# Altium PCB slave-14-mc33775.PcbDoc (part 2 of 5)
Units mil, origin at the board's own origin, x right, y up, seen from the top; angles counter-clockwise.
Board outline 6299.21 x 3937.01 mil, 6 copper layers (Top Copper, Supply, Signal Layer 1, Signal Layer 2, GND, Bot Copper), stack 69.773 mil thick; 428 components, 213 nets, 1149 pads, 1672 vias.
Unrouted connection lines stored in the file: 1.
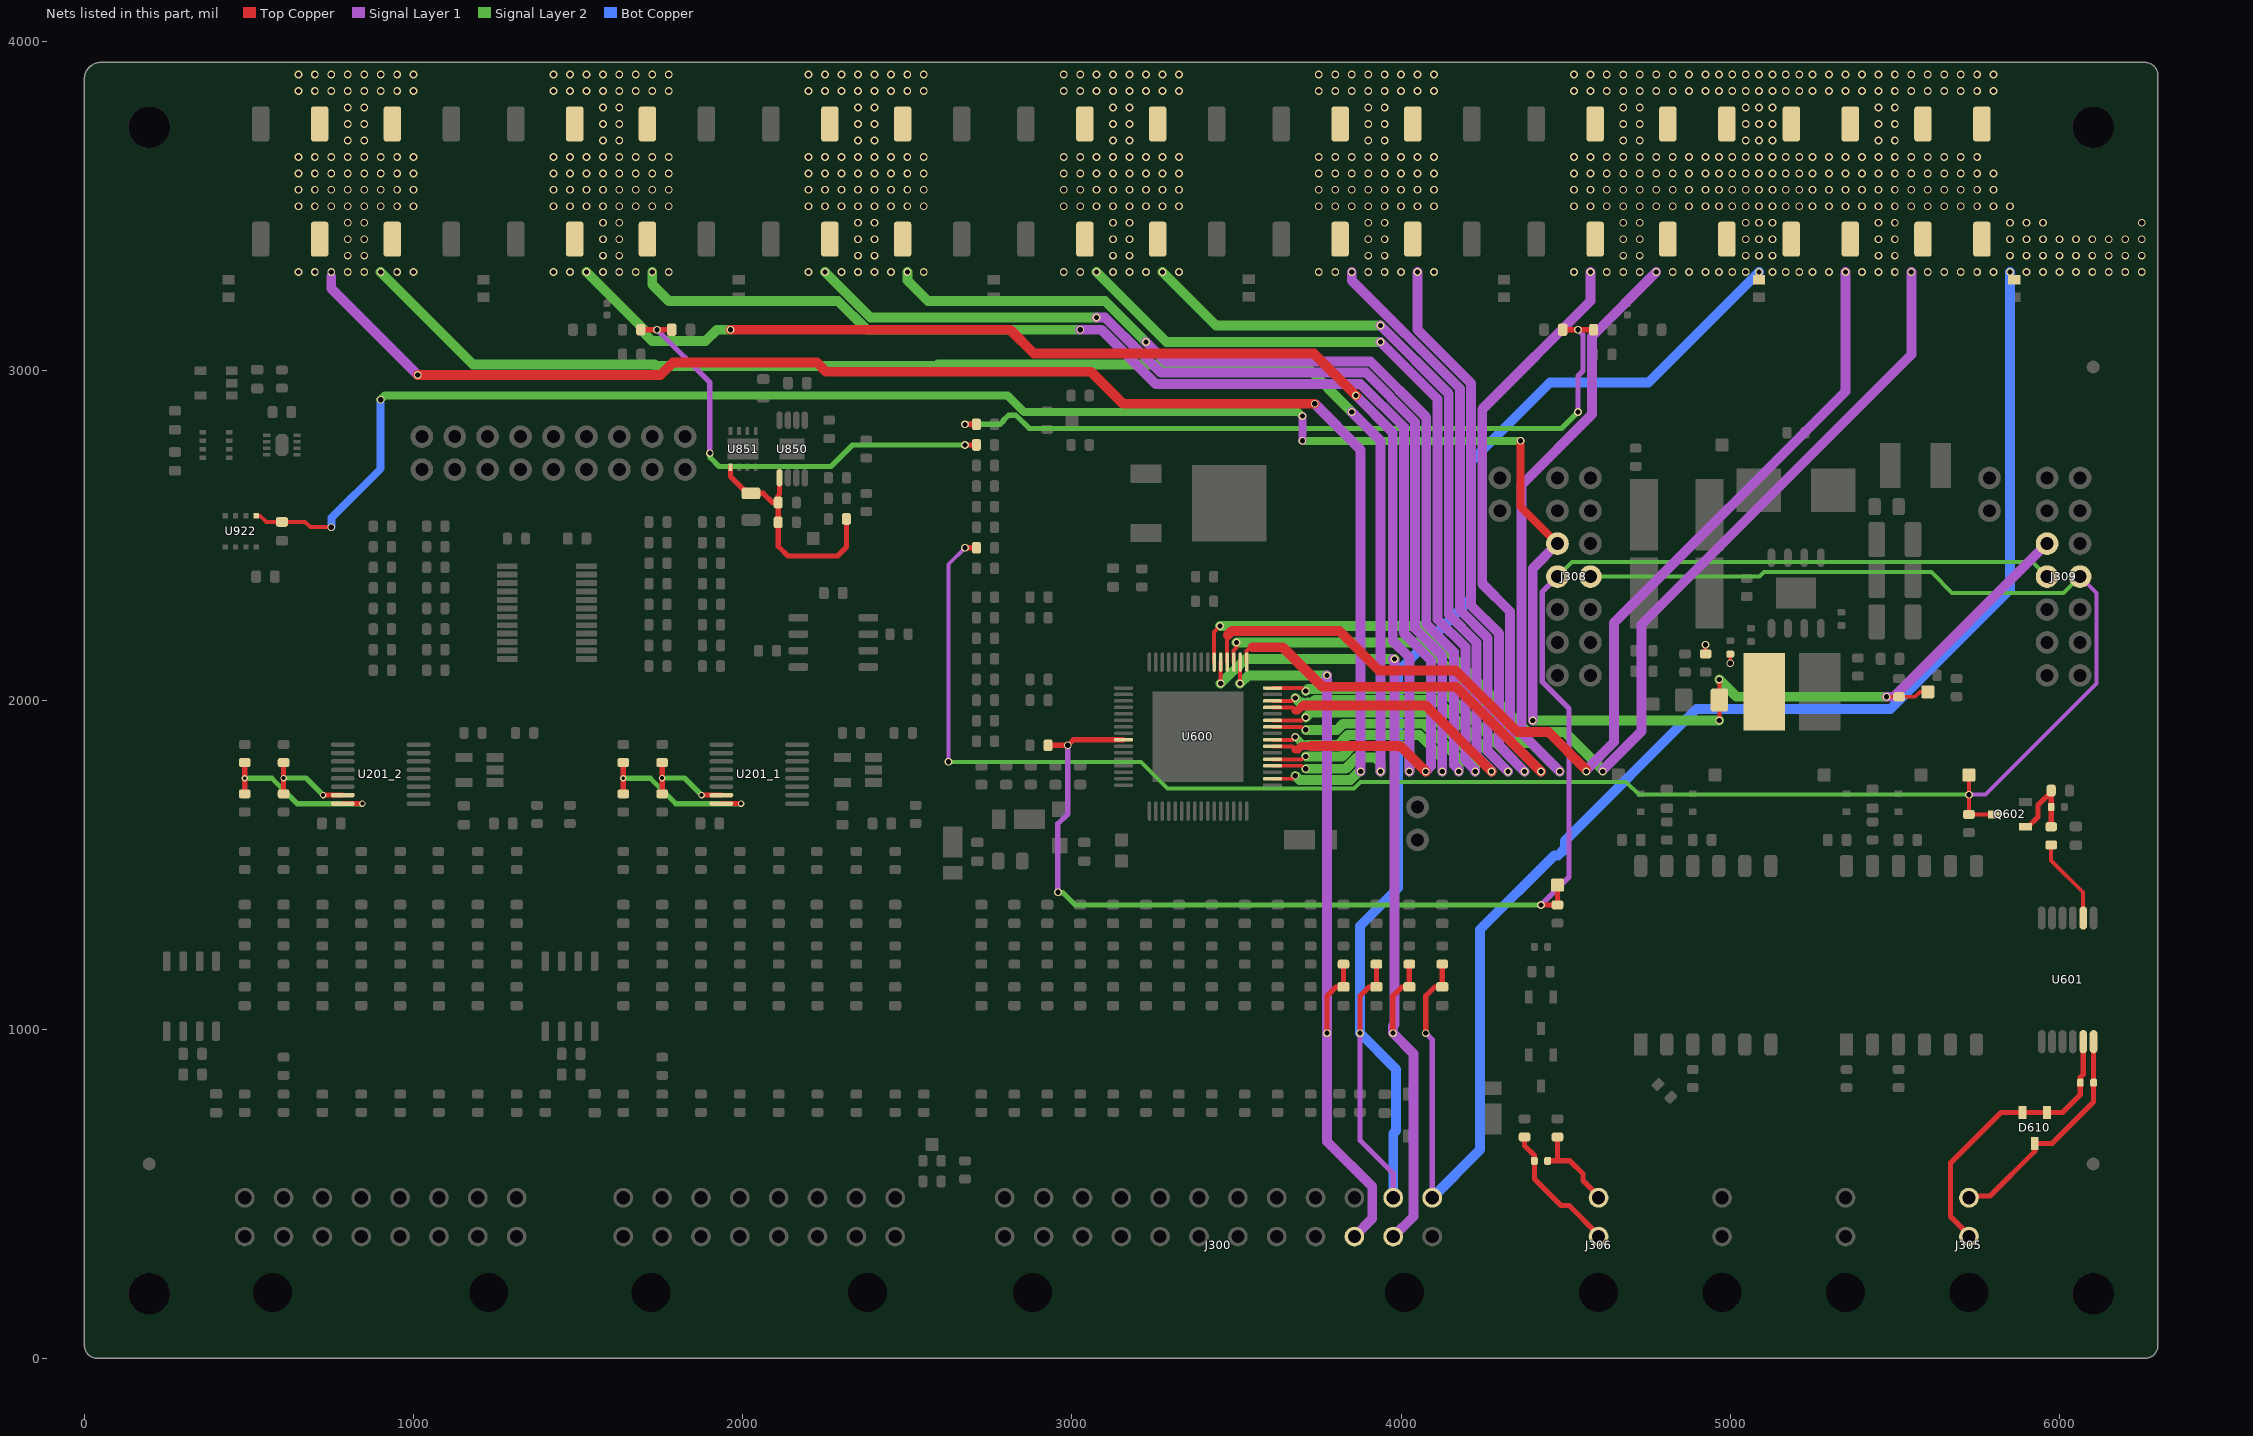
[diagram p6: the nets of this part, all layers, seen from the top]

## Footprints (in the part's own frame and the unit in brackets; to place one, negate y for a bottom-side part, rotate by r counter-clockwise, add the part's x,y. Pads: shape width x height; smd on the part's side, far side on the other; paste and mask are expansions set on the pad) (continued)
PowerDI123 [mm] "PowerDI123, 2-Leads, Body 1,78x3,70mm, IPC Medium Density"
  rect 2.4x1.5 smd: 1(-0.85,0)
  rect 1.05x1.5 smd: 2(1.525,0)
  silkscreen extent -2.05,1.05 -1.95,1.15, body extent -1.85,-0.96 1.85,0.96, height 1
PW0024A_M [mm] "SOP, 24-Leads, Body 7.9x4.5mm, Pitch 0.65mm, IPC Low Density"
  rrect22% 1.6x0.45 smd: 1(-3.05,3.575) 2(-3.05,2.925) 3(-3.05,2.275) 4(-3.05,1.625) 5(-3.05,0.975) 6(-3.05,0.325) 7(-3.05,-0.325) 8(-3.05,-0.975) 9(-3.05,-1.625) 10(-3.05,-2.275) 11(-3.05,-2.925) 12(-3.05,-3.575) 13(3.05,-3.575) 14(3.05,-2.925) 15(3.05,-2.275) 16(3.05,-1.625) 17(3.05,-0.975) 18(3.05,-0.325) 19(3.05,0.325) 20(3.05,0.975) 21(3.05,1.625) 22(3.05,2.275) 23(3.05,2.925) 24(3.05,3.575)
  silkscreen extent -3.17,-3.95 1.85,4.47, body extent -3.21,-3.9 3.21,3.9, height 1
R-PDSO-G8 [mm] "SOIC, 8-Leads, Body 4,90x3,90mm, Pitch 1,27mm, Thermal Pad 3,10x2,40mm, IPC Medium Density"
  oval 1.45x0.6 smd: 1(-2.725,1.905) 2(-2.725,0.635) 3(-2.725,-0.635) 4(-2.725,-1.905) 5(2.725,-1.905) 6(2.725,-0.635) 7(2.725,0.635) 8(2.725,1.905)
  rect 2.4x3.1 smd: 9(0,0)
  silkscreen extent -2.85,-2.5 1.6,2.88, body extent -3,-2.5 3,2.5, height 1.7
RESC1005X04N [mm] "Chip Resistor, 2-Leads, Body 1,00x0,50mm, IPC Medium Density"
  rrect50% 0.55x0.55 smd: 1(-0.45,0) 2(0.45,0)
  body extent -0.53,-0.28 0.53,0.28, height 0.4
RESC1608X05N [mm] "Chip Resistor, 2-Leads, Body 1,60x0,80mm, IPC Medium Density"
  rrect50% 0.7x0.9 smd: 1(-0.7,0) 2(0.7,0)
  body extent -0.85,-0.45 0.85,0.45, height 0.45
RESC2012X05N [mm] "Chip Resistor, 2-Leads, Body 2,00x1,20mm, IPC Medium Density"
  rrect40% 0.95x1.3 smd: 1(-0.925,0) 2(0.925,0)
  silkscreen extent -0.05,-0.55 0.05,0.55, body extent -1.05,-0.65 1.05,0.65, height 0.5
RESC5025X07N [mm] "Chip Resistor, 2-Leads, Body 5,00x2,50mm, IPC Medium Density"
  rrect30% 1.35x2.7 smd: 1(-2.275,0) 2(2.275,0)
  silkscreen extent -1.2,-1.25 1.2,1.25, body extent -2.6,-1.35 2.6,1.35, height 0.7
S1MSP1 [mm] "SODFL, 2-Leads, Body 1,78x3,70mm, IPC Medium Density"
  rect 2.4x1.5 smd: 1(0.85,0)
  rect 1.05x1.5 smd: 2(-1.525,0)
  silkscreen extent 1.73,-1.07 1.83,-0.97, body extent -1.85,-0.96 1.85,0.96, height 1
SHT3X [mm] "SON, 8-Leads, Body 2,50x2,50mm, Pitch 0,50mm, Thermal Pad 1,80x1,09mm, IPC Medium Density"
  rect 0.55x0.25 smd: 1(-1.17,0.75) 2(-1.17,0.25) 3(-1.17,-0.25) 4(-1.17,-0.75) 5(1.17,-0.75) 6(1.17,-0.25) 7(1.17,0.25) 8(1.17,0.75)
  oct 1x1.7 smd: 9(0,0)
  Top Copper region: 0,-0.849 0.5,-0.849 0.5,0.851 0,0.851
  Top Copper region: -0.499,-0.85 0.001,-0.85 0.001,0 -0.499,0
  silkscreen extent -1.9,-1.45 1.45,1.5, body extent -1.25,-1.25 1.25,1.25, height 0.9
SOD523_PESD_NEXPERIA [mm] "SODFL, 2-Leads, Body 0,80x1,60mm, IPC Medium Density"
  rect 0.5x0.6 smd: 1(-0.7,0) 2(0.7,0)
  silkscreen extent -0.9,0.55 -0.8,0.65, body extent -0.8,-0.43 0.8,0.43, height 0.65
SOIC127P600X175-8N [mm] "SOIC, 8-Leads, Body 4,90x3,90mm, Pitch 1,27mm, IPC Medium Density"
  rrect50% 1.5x0.6 smd: 1(-2.7,1.905) 2(-2.7,0.635) 3(-2.7,-0.635) 4(-2.7,-1.905) 5(2.7,-1.905) 6(2.7,-0.635) 7(2.7,0.635) 8(2.7,1.905)
  silkscreen extent -2.8,-2.45 1.55,2.8, body extent -3,-2.45 3,2.45, height 1.75
SOT95P237X110-3N [mm] "SOT23, 3-Leads, Body 2,92x2,37mm, Pitch 0,95mm, IPC Medium Density"
  rect 1x0.6 smd: D(1.2,0) G(-1.2,0.95) S(-1.2,-0.95)
  silkscreen extent -0.3,-1.5 0.7,1.5, body extent -1.32,-1.52 1.32,1.52, height 1.1
SOT-23-OT5_L [mm] "SOT23, 5-Leads, Body 2.9x1.7mm, Pitch 0.95mm, Lead Span 2.8mm, IPC High Density"
  rect 0.9x0.65 smd: 1(-1.2,0.95) 2(-1.2,0) 3(-1.2,-0.95) 4(1.2,-0.95) 5(1.2,0.95)
  silkscreen extent -1.33,-1.55 0.35,1.95, body extent -0.9,-1.55 0.9,1.55, height 1.45
SRP7028A [mm] "Bourns SRP7028A Series"
  rect 3.45x3.35 smd: 1(-2.875,0) 2(2.875,0)
  silkscreen extent -3.8,-3.45 3.8,3.45, body extent -3.45,-3.3 3.45,3.3, height 2.86
Testpoint_S1 [mm] "Testpunkt, quardratisch 1mm"
  rrect20% 1x1 smd paste-0.5: 1(0,0)
TPS7A16_VSON [mm] "SON, 8-Leads, Body 3,00x3,00mm, Pitch 0,65mm, Thermal Pad 2,40x1,49mm, IPC Medium Density"
  rect 0.6x0.3 smd: 1(-1.4,0.975) 2(-1.4,0.325) 3(-1.4,-0.325) 4(-1.4,-0.975) 5(1.4,-0.975) 6(1.4,-0.325) 7(1.4,0.325) 8(1.4,0.975)
  rect 1.65x2.4 smd: 9(0,0)
  silkscreen extent -2.15,-1.7 1.7,1.75, body extent -1.55,-1.55 1.55,1.55, height 1
TPS7A16A-Q1 [mm] "TSOP, 8-Leads, Body 3,00x3,00mm, Pitch 0,65mm, Thermal Pad 1,92x1,60mm, IPC Medium Density"
  oval 1.35x0.5 smd: 1(-2.225,0.975) 2(-2.225,0.325) 3(-2.225,-0.325) 4(-2.225,-0.975) 5(2.225,-0.975) 6(2.225,-0.325) 7(2.225,0.325) 8(2.225,0.975)
  rect 1.6x1.92 smd: 9(0,0)
  silkscreen extent -2.35,-1.55 1.15,1.9, body extent -2.45,-1.55 2.45,1.55, height 1.1
TYS6045470M-10 [mm] "Precision Wire Wound Inductor, 2-Leads, Body 6,00x6,00mm, IPC Medium Density"
  rect 3.2x6 smd: 1(-2.15,0) 2(2.15,0)
  silkscreen extent -4.05,-3.15 0.15,3.15, body extent -3.1,-3 3.1,3, height 4.8
Vishay_THJP_0603 [mm] "ThermaWick Ceramic thermal coupling, 2-Leads, Body 1,55x0,84mm, IPC Medium Density"
  rect 0.75x0.95 smd: 1(-0.675,0) 2(0.675,0)
  body extent -0.84,-0.49 0.84,0.49, height 0.89

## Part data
3.3V_DCDC 3.3V_LDO ALARM_IN ALARM_OUT enable_DCDC GND TPL_H_N TPL_H_P TPL_L_N TPL_L_P Vaux Vbat Vbat_con_ext Vddc Vin_DCDC Vmodule: "Testpoint, square"
C200_1 C200_2 C203_1 C203_2 C220_1 C220_2: library part gen_C_ceramic_1u_35V_X7R_0603, "MLCC", Capacitance=1u, Case EIA=0603, Case Metric=1608, Dielectric=X7R, Operating Temperature="-55°C - +125°C", PnP Package=0603C, PnP Value=1uF/35V/X7R, Rated Voltage=35V, Supplier Part Number 1=2906941
C201_1 C201_2 C212_1 C212_2 C213_1 C213_2 C214_1 C214_2 C215_1 C215_2 C216_1 C216_2 C217_1 C217_2 C218_1 C218_2 C219_1 C219_2 C221_1 C221_2 C400 C601 C603 C604 C605 C606 C613 C617 C807 C850 C852 C900 C920 C921 C922 C923 C924 C925: library part gen_C_ceramic_100n_100V_X7R_0603, "MLCC", Capacitance=100n, Case EIA=0603, Case Metric=1608, Dielectric=X7R, PnP Package=0603C, Rated Voltage=100V, Supplier Part Number 1=490-13420-1-ND
C202_1 C202_2 C204_1 C204_2 C205_1 C205_2 C206_1 C206_2 C207_1 C207_2 C208_1 C208_2 C209_1 C209_2 C210_1 C210_2 C211_1 C211_2 C607 C610: library part gen_C_ceramic_10n_100V_X7R_0603, "MLCC", Capacitance=10n, Case EIA=0603, Case Metric=1608, Dielectric=X7R, PnP Package=0603C, PnP Value=10nF/100V/X7R, Rated Voltage=100V, Supplier Part Number 1=1301715
C500 C501 C502 C503 C504 C505 C506 C507 C508 C509 C510 C511 C512 C513 C514 C515 C516 C517 C518 C519 C520 C521 C522 C523 C524 C525 C526 C527 C528 C529 C530 C531 C600 C700 C701 C702 C703: library part gen_C_ceramic_47n_100V_X7R_0603, "MLCC", Capacitance=47n, Case EIA=0603, Case Metric=1608, Dielectric=X7R, PnP Package=0603C, Rated Voltage=100V, Supplier Part Number 1=2478249
C602 C608 C609 C612: library part gen_C_ceramic_220p_50V_C0G_0603, "MLCC", Capacitance=220p, Case EIA=0603, Case Metric=1608, Dielectric=C0G, PnP Package=0603C, Rated Voltage=50V, Supplier Part Number 1=603-AC603JRNPO9BN221
C611: library part gen_C_ceramic_470n_50V_X7R_0603, "MLCC", Capacitance=470n, Case EIA=0603, Case Metric=1608, Dielectric=X7R, PnP Package=0603C, Rated Voltage=50V, Supplier Part Number 1=2547051
C614 C615 C616 C618: library part gen_C_ceramic_22p_50V_C0G_0402, "MLCC", Capacitance=22p, Case EIA=0402, Case Metric=1005, Dielectric=C0G, PnP Package=0402C, Rated Voltage=50V, Supplier Part Number 1=1856067, Tolerance=1%
C800 C801: library part gen_C_ceramic_15u_100V_X7R_2220, "Stacked MLCC", Capacitance=15u, Case EIA=2220, Case Metric=5750, Dielectric=X7R, Rated Voltage=100V, Supplier Part Number 1=2781468
C802 C803: library part gen_C_ceramic_1u_100V_X7R_1210, "MLCC", Capacitance=1u, Case EIA=1210, Case Metric=3225, Dielectric=X7R, Rated Voltage=100V, Supplier Part Number 1=1301722
C804: library part gen_C_ceramic_3u3_100V_X7R_1812, "MLCC", Capacitance=3u3, Case EIA=1812, Case Metric=4532, Dielectric=X7R, Rated Voltage=100V, Supplier Part Number 1=2579025
C805 C808: library part gen_C_ceramic_2n2_100V_X7R_0402, "MLCC", Capacitance=2n2, Case EIA=0402, Case Metric=1005, Dielectric=X7R, PnP Package=0402C, Rated Voltage=100V, Supplier Part Number 1=490-4911-1-ND
C806: library part gen_C_ceramic_2u2_100V_X7R_1210, "MLCC", Capacitance=2u2, Case EIA=1210, Case Metric=3225, Dielectric=X7R, Rated Voltage=100V, Supplier Part Number 1=2781417
C809: library part gen_C_ceramic_100p_200V_C0G_0402, "MLCC", Capacitance=100p, Case EIA=0402, Case Metric=1005, Dielectric=C0G, PnP Package=0402C, Rated Voltage=200V, Supplier Part Number 1=2426878, Tolerance=5%
C810: library part gen_C_ceramic_22u_6V3_X7R_1206, "MLCC", Capacitance=22u, Case EIA=1206, Case Metric=3216, Dielectric=X7R, Rated Voltage=6.3V, Supplier Part Number 1=2672216
C851: library part gen_C_ceramic_2u2_10V_X7R_0805, "MLCC", Capacitance=2u2, Case EIA=0805, Case Metric=2012, Dielectric=X7R, Rated Voltage=10V, Supplier Part Number 1=2478259
D600 D601 D608: "Schottky Diode", Breakdown Voltage=100V, Continuous Forward Current=1A, Manufacturer="Diodes Inc.", Operating Temperature="−55°C - +175°C", PnP Package=POWERDI123, Supplier Part Number 1=621-DFLS1-100Q-7
D602: "400W Transient Voltage Suppressor", Breakdown Voltage=70.20V, Manufacturer=Nexperia, Operating Temperature="-55°C - +150°C", Part Name=PTVSxS1UR, Supplier Part Number 1=771-PTVS60VS1UR115
D603: "1.0A surface mount glass passivated rectifier", Breakdown Voltage=1000V, Continuous Forward Current=1A, Manufacturer="Diodes Inc.", Operating Temperature="-55°C - +150°C", Supplier Part Number 1=621-S1MSP1-7
D604 D605 D606 D607: "Very low capacitance bidirectional ESD protection diode", Breakdown Voltage=6.8V, Manufacturer=Nexperia, Operating Temperature="-55°C - +150°C", PnP Package=SOD523, Supplier Part Number 1=771-PESD5V0V1BB115
D609 D610: "ESD-Schutzbaustein", Breakdown Voltage=8V, Manufacturer="ON Semiconductor", PnP Package=SOT23-3, Supplier Part Number 1=2317483
FD_LL FD_LR FD_UR: library part Fiducial_2
IC920: library part CMP-0192-00211-1, "2-Wire High-Accuracy Temperature Sensor, Slave Address 000, 5-Pin SOT-23, -55°C to +125°C Temperature, Tape and Reel"
J300: "Micro-Fit 3.0 Right Angle Header, 3.00mm Pitch, Dual Row, 24 Circuits, with Snap-in Plastic Peg PCB Lock, Tin, Glow Wire Capable, Black, 43045-2400", Manufacturer=Molex, Operating Temperature="-40°C - +105°C", Part Name=MicroFit, Rated Current=8.5A, Rated Voltage=600V, Supplier Part Number 1=1012245
J301 J302 J305 J306: "Micro-Fit 3.0 Right Angle Header, 3.00mm Pitch, Dual Row, 2 Circuits, with Snap-in Plastic Peg PCB Lock, Tin, Glow Wire Capable, Black, 43045-0200", Manufacturer=Molex, Operating Temperature="-40°C - +105°C", Part Name=MicroFit, Rated Current=8.5A, Rated Voltage=600V, Supplier Part Number 1=1012251
J303: "Standard Pinheader, THD, gerade, 2.54mm, 2-reihig", Operating Temperature="−40 °C - +105 °C", Part Name=PinHeader, Rated Current=3A, Rated Voltage=250V, Supplier Part Number 1=2025256
J304 J307: "Micro-Fit 3.0 Right Angle Header, 3.00mm Pitch, Dual Row, 16 Circuits, with Snap-in Plastic Peg PCB Lock, Tin, Glow Wire Capable, Black, 43045-1600", Manufacturer=Molex, Operating Temperature="-40°C - +105°C", Part Name=MicroFit, Rated Current=8.5A, Rated Voltage=600V, Supplier Part Number 1=9961380
J308 J309: "Standard Pinheader, THD, gerade, 2.54mm, 2-reihig", Operating Temperature="−40 °C - +105 °C", Part Name=PinHeader, Rated Current=3A, Rated Voltage=250V, Supplier Part Number 1=200-TSW10707GD
J310 J311 J312: "Standard Pinheader, THD, gerade, 2.54mm", Operating Temperature="−40 °C - +105 °C", Part Name=PinHeader, Rated Current=3A, Rated Voltage=250V, Supplier Part Number 1=2505044
L800: library part SRP7028A-R47M, "FIXED IND 470NH 17.5A 4.2 MOHM", Manufacturer="Bourns Inc", Operating Temperature="-40°C - +150°C", Rated Current=17.5A, Saturation Current=26A, Supplier Part Number 1=SRP7028A-R47MCT-ND
L801: library part TYS6045470M-10, "Power Inductor", Manufacturer="Laird-Signal Integrity Products", Operating Temperature="-55°C - +150°C", Rated Current=1.2A, Saturation Current=1.4A, Supplier Part Number 1=240-2745-1-ND
LD600 LD601 LD800 LD850: library part LED_0603_green_AECQ, "TLMG1100-GS08", Breakdown Voltage=5V, Continuous Forward Current=20mA, Forward Voltage @ 20mA=2.1V, Manufacturer=Vishay, Operating Temperature="-40°C - 100°C", PnP Package=LED_0603, Supplier Part Number 1=2293494
MP_LL MP_LR MP_UL MP_UR: "Hole, M3, with Isolation"
Q600: "100V, 3A NPN high power bipolar transistor", Manufacturer=Nexperia, Operating Temperature="-55°C - +150°C", Part Name=MJD31CA, Supplier Part Number 1=771-MJD31CAJ
Q601 Q602: "MOSFET-Transistor, n-Kanal, 1.6 A, 100 V, 0.250 ohm", Manufacturer=Diodes, Maximum Continous Drain Current (25°C)=1.6A, Maximum Drain-Source Voltage=100V, Operating Temperature="-55°C - +150°C", Part Name=NMOS, Supplier Part Number 1=DMN10H220L-7DICT-ND
R100 R200_1 R200_2 R201_1 R201_2 R202_1 R202_2 R203_1 R203_2 R204_1 R204_2 R205_1 R205_2 R210_1 R210_2 R211_1 R211_2 R212_1 R212_2 R213_1 R213_2 R214_1 R214_2 R215_1 R215_2 R216_1 R216_2 R217_1 R217_2 R230_1 R230_2 R232_1 R232_2 R516 R517 R518 R519 R520 R521 R522 R523 R524 R525 R526 R601 R602 R603 R606 R607 R608 R609 R610 R612 R613 R614 R615 R619 R620 R622 R623 R624 R625 R626 R629 R630 R631 R633 R635 R636 R637 R639 R640 R801 R803 R807 R850 R851 R853: library part gen_R_0R_0603, "SMD Resistor 0R 0603", Case EIA=0603, Case Metric=1608, Maximum Working Voltage=75V, Operating Temperature="-55°C - +155°C", PnP Package=0603R, Power=0.1W, Supplier Part Number 1=2616580
R206_1 R206_2 R207_1 R207_2 R208_1 R208_2 R209_1 R209_2 R218_1 R218_2 R219_1 R219_2 R220_1 R220_2 R221_1 R221_2 R500 R501 R502 R503 R504 R505 R506 R507 R508 R509 R510 R511 R512 R513 R514 R515 R700 R701 R702 R703 R810 R916 R920: library part gen_R_10k_0603, "SMD Resistor 10k 0603", Case EIA=0603, Case Metric=1608, Maximum Working Voltage=75V, Operating Temperature="-55°C - +155°C", PnP Package=0603R, Power=0.1W, Supplier Part Number 1=2073349, Tolerance=1%
R222_1 R222_2 R223_1 R223_2 R224_1 R224_2 R225_1 R225_2 R226_1 R226_2 R227_1 R227_2 R228_1 R228_2 R229_1 R229_2 R231_1 R231_2: library part gen_R_1k_0603, "SMD Resistor 1k 0603", Case EIA=0603, Case Metric=1608, Maximum Working Voltage=75V, Operating Temperature="-55°C - +155°C", PnP Package=0603R, Power=0.1W, Supplier Part Number 1=1652848, Tolerance=1%
R400 R401 R616 R617 R627 R641: library part gen_R_5k1_0603, "SMD Resistor 5k1 0603", Case EIA=0603, Case Metric=1608, Maximum Working Voltage=75V, Operating Temperature="-55°C - +155°C", PnP Package=0603R, Power=0.1W, Supplier Part Number 1=667-ERJ-3GEYJ512V, Tolerance=5%
R600: library part gen_R_10R_0805, "SMD Resistor 10R 0805", Case EIA=0805, Case Metric=2012, Maximum Working Voltage=150V, Operating Temperature="-55°C - +155°C", PnP Package=0805R, Power=0.125W, Supplier Part Number 1=1750728, Tolerance=1%
R604: library part gen_R_270R_0603, "SMD Resistor 270R 0603", Case EIA=0603, Case Metric=1608, Maximum Working Voltage=75V, Operating Temperature="-55°C - +155°C", PnP Package=0603R, Power=0.1W, Supplier Part Number 1=2141320, Tolerance=1%
R605: library part gen_R_2k7_0603, "SMD Resistor 2k7 0603", Case EIA=0603, Case Metric=1608, Maximum Working Voltage=75V, Operating Temperature="-55°C - +155°C", PnP Package=0603R, Power=0.1W, Tolerance=1%
R611 R621 R628 R632 R634 R642: library part gen_R_150R_0603, "SMD Resistor 150R 0603", Case EIA=0603, Case Metric=1608, Maximum Working Voltage=75V, Operating Temperature="-55°C - +155°C", PnP Package=0603R, Power=0.1W, Supplier Part Number 1=2303076, Tolerance=1%
R618: library part gen_R_4R53_0603, "SMD Resistor 4R53 0603", Case EIA=0603, Case Metric=1608, Maximum Working Voltage=75V, Operating Temperature="-55°C - +155°C", PnP Package=0603R, Power=0.1W, Tolerance=1%
R638 R643 R808 R900 R901 R902 R903 R904 R905 R906 R907 R908 R909 R910 R911 R912 R913 R914 R915 R917 R918 R919 R921 R922 R923 R924 R925 R926 R927 R928 R929 R930 R931 R932 R933: library part gen_R_100k_0603, "SMD Resistor 100k 0603", Case EIA=0603, Case Metric=1608, Maximum Working Voltage=75V, Operating Temperature="-55°C - +155°C", PnP Package=0603R, Power=0.1W, Supplier Part Number 1=2303232, Tolerance=1%
R704 R705: library part gen_R_10k_NTC_0402, "SMD Resistor 10k NTC 0402", Case EIA=0402, Maximum Working Voltage=50V, Operating Temperature="-40°C - +150°C", Power=0.150W, Supplier Part Number 1=2432559
R706 R707 R708 R709 R710 R711 R712 R713: library part Vishay_THJP_0603, "ThermaWick thermal coupling 0603", Case EIA=0603, Maximum Working Voltage=1.5kV, Supplier Part Number 1=71-THJP0603AST1
R714 R715 R716 R717 R718 R719 R720 R721 R722 R723 R724 R725 R726 R727 R728 R729 R730 R731 R732 R733 R734 R735 R736 R737 R738 R739 R740 R741: library part gen_R_68R_2010, "SMD Resistor 68R 2010", Case EIA=2010, Case Metric=5025, Maximum Working Voltage=200V, Operating Temperature="-55°C - +155°C", PnP Package=2010R, Power=0.75W, Supplier Part Number 1=2323988, Tolerance=1%
R800: library part gen_R_100R_0603, "SMD Resistor 100R 0603", Case EIA=0603, Case Metric=1608, Maximum Working Voltage=75V, Operating Temperature="-55°C - +155°C", PnP Package=0603R, Power=0.1W, Supplier Part Number 1=P100HCT-ND, Tolerance=1%
R802: library part gen_R_0R1_0805, "SMD Resistor 0R1 0805", Case EIA=0805, Maximum Working Voltage=150V, Operating Temperature="-55°C - +155°C", Power=250mW, Supplier Part Number 1=2824733
R804 R854: library part gen_R_240R_0603, "SMD Resistor 240R 0603", Case EIA=0603, Case Metric=1608, Maximum Working Voltage=75V, Operating Temperature="-55°C - +155°C", PnP Package=0603R, Power=0.1W, Supplier Part Number 1=667-ERJ-3EKF2400V, Tolerance=1%
R805: library part gen_R_287k_0603, "SMD Resistor 287k 0603", Case EIA=0603, Case Metric=1608, Maximum Working Voltage=75V, Operating Temperature="-55°C - +155°C", PnP Package=0603R, Power=0.1W, Supplier Part Number 1=667-ERJ-3EKF2873V, Tolerance=1%
R806: library part gen_R_174k_0603, "SMD Resistor 174k 0603", Case EIA=0603, Case Metric=1608, Maximum Working Voltage=75V, Operating Temperature="-55°C - +155°C", PnP Package=0603R, Power=0.1W, Supplier Part Number 1=667-ERJ-3EKF1743V, Tolerance=1%
R809: library part gen_R_27k4_0603, "SMD Resistor 27k4 0603", Case EIA=0603, Case Metric=1608, Maximum Working Voltage=75V, Operating Temperature="-55°C - +155°C", PnP Package=0603R, Power=0.1W, Supplier Part Number 1=667-ERJ-3EKF2742V, Tolerance=1%
R852: library part gen_R_1M_0603, "SMD Resistor 1M 0603", Case EIA=0603, Case Metric=1608, Maximum Working Voltage=75V, Operating Temperature="-55°C - +155°C", PnP Package=0603R, Power=0.1W, Supplier Part Number 1=1469746, Tolerance=1%
T600 T601: "Pulse HM2102NLT BMS Transformer", Manufacturer=Pulse, Operating Temperature="-40°C - +125°C", Supplier Part Number 1=673-HM2102NLT
U200_1 U200_2: "Ultralow Noise, High Accuracy 4.096V Reference", Manufacturer="Analog Devices", Operating Temperature="−40°C - +125°C", PnP Package=SO-8, Supplier Part Number 1=2112692
U201_1 U201_2: library part CMP-0798-00197-1, "CMOS, Low Voltage, 2-Wire Serially Controlled, Matrix Switch, -40 to 85 degC, 16-pin SOP (RU-16), Tube", Manufacturer="Analog Devices"
U202_1 U202_2: library part CMP-0384-01512-2, "Single Channel RRIO Operational Amplifier, 2.5 MHz BW, 1 V/us SR, Industrial, 5-pin SOT23 (RJ-5), Reel", Amplifiers Per Package=1, Generic Part Number=AD8628, Input Bias Current=30pA, Input Offset Voltage=1uV, Manufacturer="Analog Devices"
U400: "Automotive 2-Mbit serial I²C  / bus EEPROM with 1 MHz clock", Manufacturer=STMicroelectronics, Operating Temperature="-40°C - +125°C", PnP Package=SO8N, Supplier Part Number 1=497-16238-1-ND
U600: "14 Cells Battery Cell Controller IC", Manufacturer=NXP, Operating Temperature="−40°C - +125°C"
U601: "15MBd Dual-channel Bi-directional Optocoupler", Manufacturer=Broadcom, Operating Temperature="-40°C - +125°C", PnP Package=12-BSOP, Supplier Part Number 1=516-3808-ND
U800: "100-V Input, 0.5-A SynchronousBuck DC/DCConverterwith Ultra-lowIQ", Manufacturer="Texas Instruments", Operating Temperature="-40°C - +125°C", Supplier Part Number 1=296-53561-1-ND
U850: "Automotive 60-V, 5-µA IQ, 100-mA low-dropout (LDO) voltage regulator with enable and power good", Manufacturer="Texas Instruments", Operating Temperature="-40°C - +125°C", Part Name=TPS7A16A-Q1, PnP Package=HVSSOP-8, Supplier Part Number 1=296-TPS7A1633AQDGNRQ1TR-ND
U851: "Automotive 60-V, 5-µA IQ, 100-mA low-dropout (LDO) voltage regulator with enable and power good", Manufacturer="Texas Instruments", Operating Temperature="-40°C - +125°C", Part Name=TPS7A16A-Q1, PnP Package=VSON-8, Supplier Part Number 1="595-TPS7A1633DRBR / 595-TPS7A1633DRBR / 595-TPS7A1633DRBR"
U900: library part CMP-0314-00251-2, "Remote 16-Bit I2C and SMBus, Low-Power I/O Expander with Interrupt Output, Reset & Config. Register, 1.65 to 5.5 V, -40 to 85 degC, 24-pin TSSOP (PW), Green (RoHS & no Sb/Br)", 5V Tolerant I/O=Yes, Manufacturer="Texas Instruments", Max Frequency(kHz)=400
U920: "Low power pressure, temperature & humidity sensor", Manufacturer="Bosch Sensortec", Operating Temperature="-40°C - +85°C", PnP Package=LGA, Supplier Part Number 1=828-1063-1-ND
U921: "Humidity/Temp Sensor, Digital, Dfn-8", Manufacturer=Sensirion, Operating Temperature="-40°C - +125°C", PnP Package=DFN, Supplier Part Number 1=2886656
U922: "Low power gas, pressure, temperature & humidity sensor", Manufacturer="Bosch Sensortec", Operating Temperature="-40°C - +85°C", PnP Package=LGA, Supplier Part Number 1=828-1077-1-ND

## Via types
v1: diameter 23.62, hole 15.75, Top Copper to Bot Copper, 1585 vias
v2: diameter 19.68, hole 11.81, Top Copper to Bot Copper, 87 vias

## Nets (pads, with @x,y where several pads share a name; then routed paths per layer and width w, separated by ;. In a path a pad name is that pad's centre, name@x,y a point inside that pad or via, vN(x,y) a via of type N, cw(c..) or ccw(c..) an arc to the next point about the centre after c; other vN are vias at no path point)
3.3V_LDO: C851.2 R850.1 R852.2 R853.2 U850.1 U851.1 | length 731.7
  Top Copper w16: U851.1@1962.5,2707.38 1962.5,2679.53 2014.17,2627.85 2062.04,2627.85 2089.9,2600 R852.2@2107.68,2600 ; R850.1@2107.38,2539.79 R850.1@2107.53,2539.94 ; R852.2@2107.53,2599.85 R852.2@2107.68,2600 ; U850.1@2111.61,2674.9 2111.61,2625.65 2107.68,2621.72 R852.2@2107.68,2600 ; R853.2@2315.06,2550 2315.06,2465.06 2287.5,2437.5 2137.5,2437.5 2107.68,2467.32 R850.1@2107.68,2539.79 R852.2@2107.68,2600
+3.3V: 3.3V_DCDC.1 C808.2 C810.2 C923.2 J308.10 J309.10 L801.2 R801.2 R806.2 U922.8 | length 7276.2
  Top Copper w12: U922.8@522.24,2559.74 534.12,2559.74 552.82,2541.04 C923.2@600,2541.04 670.58,2541.04 686.62,2525 v1(750,2525) ; R806.2@4925,2140.06 v1(4925,2167.95) ; v1(4966.63,1937.5) C810.2@4966.63,2000 v1(4966.63,2062.5) ; v1(5000,2111.87) C808.2@5000,2139.76 ; v1@5476.28,2011.22 5477.56,2009.94 R801.2@5512.5,2009.94 5561.26,2009.94 5576.32,2025 3.3V_DCDC.1@5600,2025
  Top Copper w24: v1(4362.5,2787.5) 4362.5,2587.5 J308.10@4475,2475
  Signal Layer 1 w24: v1(3700,2787.5) v1(3700,2862.5)
  Signal Layer 1 w30: v1(4400,1937.5) 4400,2400 J308.10@4475,2475 ; v1(5475,2009.94) 5497.44,2009.94 J309.10@5962.5,2475
  Signal Layer 2 w24: v1(900,2912.5) 912.5,2925 2804.52,2925 2854.52,2875 3687.5,2875 v1(3700,2862.5) ; v1(3700,2787.5) v1(4362.5,2787.5)
  Signal Layer 2 w30: v1(4400,1937.5) v1(4966.63,1937.5) ; v1(4966.63,2062.5) 5019.19,2009.94 v1(5475,2009.94)
  Bot Copper w24: v1(750,2525) 750,2552.98 900,2702.98 v1(900,2912.5)
A0_1: R201_1.1 R204_1.2 U201_1.16 | length 544.5
  Top Copper w15: U201_1.16@1934.84,1685.43 v2(1994.69,1685.43)
  Top Copper w16: R204_1.2@1637.01,1715.06 v2(1637.01,1762.5) R201_1.1@1637.01,1809.94
  Signal Layer 2 w16: v2(1637.01,1762.5) 1719.01,1762.5 1796.33,1685.18 1994.43,1685.18 v2(1994.69,1685.43)
A0_2: R201_2.1 R204_2.2 U201_2.16 | length 544.5
  Top Copper w15: U201_2.16@784.84,1685.43 v2(844.69,1685.43)
  Top Copper w16: R204_2.2@487.01,1715.06 v2(487.01,1762.5) R201_2.1@487.01,1809.94
  Signal Layer 2 w16: v2(487.01,1762.5) 569.01,1762.5 646.33,1685.18 844.43,1685.18 v2(844.69,1685.43)
A1_1: R202_1.1 R205_1.2 U201_1.15 | length 297.9
  Top Copper w15: v2(1875,1711.02) U201_1.15@1934.84,1711.02
  Top Copper w16: R205_1.2@1755,1715.06 1756.12,1715.06 1755,1716.18 v2(1755,1763.06) R202_1.1@1755,1809.94
  Signal Layer 2 w16: v2(1755,1763.06) 1822.97,1763.06 v2(1875,1711.02)
A1_2: R202_2.1 R205_2.2 U201_2.15 | length 297.9
  Top Copper w15: v2(725,1711.02) U201_2.15@784.84,1711.02
  Top Copper w16: R205_2.2@605,1715.06 606.12,1715.06 605,1716.18 v2(605,1763.06) R202_2.1@605,1809.94
  Signal Layer 2 w16: v2(605,1763.06) 672.97,1763.06 v2(725,1711.02)
AL_IN._N: C616.2 D610.3 J305.2 U601.12 | length 694.2
  Top Copper w16: J305.2@5725,492.99 5788.92,492.99 5925,629.07 D610.3@5925,652.76 5977.76,652.76 6103.74,778.74 C616.2@6103.74,837.5 U601.12@6103.74,962.01
AL_IN._P: C616.1 D610.1 D610.2 J305.1 U601.11 | length 887.3
  Top Copper w16: J305.1@5725,375 5668.69,431.31 5668.69,593.69 5822.24,747.24 D610.2@5887.6,747.24 D610.1@5962.4,747.24 6009.74,747.24 6063.58,801.08 C616.1@6063.58,837.5 6063.58,853.7 6072.24,862.37 U601.11@6072.24,962.01
AL_OUT._N: C614.1 J306.2 R632.2 | length 283.4
  Top Copper w16: C614.1@4445.08,600 4475,600 ; R632.2@4475,672.44 4475,600 ; J306.2@4600,492.99 4552.29,540.71 4552.29,560.71 4512.99,600 4475,600
AL_OUT._P: C614.2 J306.1 R628.2 | length 405.3
  Top Copper w16: R628.2@4375,672.44 4375,646.13 4404.92,616.2 C614.2@4404.92,600 4404.92,545.08 4485.75,464.25 4510.75,464.25 J306.1@4600,375
ALARM_IN: ALARM_IN.1 J308.7 J309.7 Q602.D R607.1 R641.2 | length 6474
  Top Copper w12: ALARM_IN.1@5725,1772.24 v1(5725,1712.5) R641.2@5725,1652.46 Q602.D@5802.76,1652.46
  Top Copper w16: v1(2675,2462.5) R607.1@2709.94,2462.5
  Signal Layer 1 w12: v1(2625,1812.5) 2625,2412.5 v1(2675,2462.5) ; v1(5725,1712.5) 5775,1712.5 6112.5,2050 6112.5,2325 J309.7@6062.5,2375
  Signal Layer 2 w12: v1(2625,1812.5) 2625.81,1811.69 3209.91,1811.69 3290.02,1731.58 3856.58,1731.58 3876.45,1751.45 4683.15,1751.45 4722.1,1712.5 v1(5725,1712.5) ; J308.7@4575,2375 5088.5,2375 5101.81,2388.31 5610.69,2388.31 5674,2325 6012.5,2325 J309.7@6062.5,2375
Alarm_in_filtered: C618.2 Q602.G R642.2 R643.1 | length 252.8
  Top Copper w16: Q602.G@5897.24,1615.06 5905.12,1615.06 5934.67,1644.61 5934.67,1680.73 R643.1@5975,1721.06 ; R642.2@5975,1615.06 C618.2@5975,1675 R643.1@5975,1721.06 ; R643.1@5975,1725 R643.1@5975,1721.06
Alarm_in_unfiltered: R642.1 U601.2 | length 262.2
  Top Copper w12: R642.1@5975,1559.94 5975,1512.5 6072.24,1415.26 U601.2@6072.24,1337.99
ALARM_OUT: ALARM_OUT.1 J308.8 J309.8 R627.2 R634.1 U600.57 | length 4898.3
  Top Copper w16: R627.2@2927.56,1862.5 v1(2987.5,1862.5) 3004.04,1879.04 U600.57@3156.59,1879.04 ; v1(4425,1377.56) R634.1@4475,1377.56 ALARM_OUT.1@4475,1437.5
  Signal Layer 1 w16: v1(2957.3,1415.92) 2957.3,1624.11 2987.5,1654.31 v1(2987.5,1862.5) ; v1(4425,1377.56) 4509.81,1462.36 4509.81,1974.51 4428.55,2055.76 4428.55,2328.55 J308.8@4475,2375
  Signal Layer 2 w12: J308.8@4475,2375 4519.45,2419.45 5918.05,2419.45 J309.8@5962.5,2375
  Signal Layer 2 w16: v1(2957.3,1415.92) 2958.76,1414.47 2973.03,1414.47 3009.94,1377.56 v1(4425,1377.56)
BAL.CB_HI2: R715.2 R729.2 U600.36 | length 3193.4
  Top Copper w12: U600.36@3471.56,2115.26 3471.56,2195.79 3475,2199.23 3475,2200
  Top Copper w30: 3473.81,2198.04 3475,2199.23 3485.58,2209.81 3812.88,2209.81 3932.51,2090.19 4165.38,2090.19 4352.88,1902.69 4447.31,1902.69 v1@4562.5,1787.5
  Signal Layer 1 w30: v1@4562.5,1787.5 4647.24,1872.24 4647.24,2234.74 5350,2937.5 v1(5350,3300)
  other v1: 4562.5,1783.26 5300,3300 5400,3300 5450,3300 5450,3350 5450,3400 5450,3450 5300,3500 5350,3500 5400,3500 5450,3500 5300,3550 5350,3550 5400,3550 5450,3550 5300,3600 5350,3600 5400,3600 5450,3600 5300,3650 5350,3650 5400,3650 5450,3650 5450,3700 5450,3750 5450,3800 5300,3850 5350,3850 5400,3850 5450,3850 5300,3900 5350,3900 5400,3900 5450,3900
BAL.CB_HI4: R717.2 R731.2 U600.33 | length 2818.7
  Top Copper w12: U600.33@3530.61,2115.26 3530.61,2148.78 3542.1,2160.28 3547.78,2160.28 3550,2162.5
  Top Copper w30: 3547.78,2160.28 3640.49,2160.28 3760.58,2040.19 4167.3,2040.19 4424.23,1783.26 v1(4425,1783.26)
  Signal Layer 1 w30: v1(4425,1783.26) 4331.19,1877.07 4331.19,2268.81 4246.55,2353.45 4246.55,2883.28 4575,3211.73 v1(4575,3300)
  other v1: 4525,3300 4625,3300 4675,3300 4675,3350 4675,3400 4675,3450 4525,3500 4575,3500 4625,3500 4675,3500 4525,3550 4575,3550 4625,3550 4675,3550 4525,3600 4575,3600 4625,3600 4675,3600 4525,3650 4575,3650 4625,3650 4675,3650 4675,3700 4675,3750 4675,3800 4525,3850 4575,3850 4625,3850 4675,3850 4525,3900 4575,3900 4625,3900 4675,3900
BAL.CB_HI6: R719.2 R733.2 U600.30 | length 2531.2
  Top Copper w12: U600.30@3609.35,1997.15 3669.39,1997.15 v1(3678.45,2006.2)
  Signal Layer 1 w30: v1(3850,3300) 3850,3275 4178.55,2946.45 4178.55,2273.37 4263.19,2188.73 4263.19,1845.07 v1(4325,1783.26)
  Signal Layer 2 w24: 3700,1992.8 3712.15,1992.8 3715.15,1995.8 3733.3,1995.8 3737.5,2000
  Signal Layer 2 w30: v1(3678.45,2006.2) 3691.85,1992.8 3700,1992.8 ; 3737.5,2000 4108.26,2000 v1(4325,1783.26)
  other v1: 3750,3300 3800,3300 3900,3300 3900,3350 3900,3400 3900,3450 3750,3500 3800,3500 3850,3500 3900,3500 3750,3550 3800,3550 3850,3550 3900,3550 3750,3600 3800,3600 3850,3600 3900,3600 3750,3650 3800,3650 3850,3650 3900,3650 3900,3700 3900,3750 3900,3800 3750,3850 3800,3850 3850,3850 3900,3850 3750,3900 3800,3900 3850,3900 3900,3900
BAL.CB_HI8: R721.2 R735.2 U600.27 | length 3095
  Top Copper w12: U600.27@3609.35,1938.09 3698.13,1938.09 3707.04,1947 v1(3710.19,1947)
  Signal Layer 1 w30: v1(3937.5,3087.5) 4110.55,2914.45 4110.55,2245.2 4195.19,2160.56 4195.19,1816.9 4225,1787.09 v1(4225,1783.26)
  Signal Layer 2 w30: v1(3075,3300) 3287.5,3087.5 v1(3937.5,3087.5) ; v1(3710.19,1947) 3725,1961.81 4083.59,1961.81 4225,1820.4 v1(4225,1783.26)
  other v1: 2975,3300 3025,3300 3125,3300 3125,3350 3125,3400 3125,3450 2975,3500 3025,3500 3075,3500 3125,3500 2975,3550 3025,3550 3075,3550 3125,3550 2975,3600 3025,3600 3075,3600 3125,3600 2975,3650 3025,3650 3075,3650 3125,3650 3125,3700 3125,3750 3125,3800 2975,3850 3025,3850 3075,3850 3125,3850 2975,3900 3025,3900 3075,3900 3125,3900
BAL.CB_HI10: R723.2 R737.2 U600.24 | length 3688.6
  Top Copper w12: U600.24@3609.35,1879.04 3669.39,1879.04 v1(3678.45,1888.09)
  Signal Layer 1 w30: v1(3075,3162.5) 3100.77,3162.5 3210.58,3052.69 3211.73,3052.69 3269.81,2994.6 3892.9,2994.6 4042.55,2844.95 4042.55,2217.03 4125,2134.58 v1(4125,1783.26)
  Signal Layer 2 w24: v1(3678.45,1888.09) 3702.84,1863.7 3714.28,1863.7
  Signal Layer 2 w30: v1(2250,3300) 2387.5,3162.5 v1(3075,3162.5) ; 3714.28,1863.7 3807.95,1863.7 3838.06,1893.81 4055.42,1893.81 4125,1824.23 v1(4125,1783.26)
  other v1: 2200,3300 2300,3300 2350,3300 2350,3350 2350,3400 2350,3450 2200,3500 2250,3500 2300,3500 2350,3500 2200,3550 2250,3550 2300,3550 2350,3550 2200,3600 2250,3600 2300,3600 2350,3600 2200,3650 2250,3650 2300,3650 2350,3650 2350,3700 2350,3750 2350,3800 2200,3850 2250,3850 2300,3850 2350,3850 2200,3900 2250,3900 2300,3900 2350,3900
BAL.CB_HI12: R725.2 R739.2 U600.21 | length 4235.8
  Top Copper w12: U600.21@3609.35,1819.98 3698.13,1819.98 3707.04,1828.89 v1(3710.19,1828.89)
  Top Copper w30: v1(1962.5,3125) 2812.5,3125 2884.81,3052.69 3734.81,3052.69 v1(3862.5,2925)
  Signal Layer 1 w30: v1(3862.5,2925) 3974.55,2812.95 3974.55,2179.49 4025,2129.04 v1(4025,1783.26)
  Signal Layer 2 w30: v1(1525,3300) 1704.42,3120.58 1704.42,3110.58 1724.81,3090.19 1886.64,3090.19 1921.45,3125 v1(1962.5,3125) ; v1(3710.19,1828.89) 3821.22,1828.89 3852.14,1859.81 4007.43,1859.81 4025,1842.24 v1(4025,1783.26) v1@4025,1782.45
  other v1: 1425,3300 1475,3300 1575,3300 1575,3350 1575,3400 1575,3450 1425,3500 1475,3500 1525,3500 1575,3500 1425,3550 1475,3550 1525,3550 1575,3550 1425,3600 1475,3600 1525,3600 1575,3600 1425,3650 1475,3650 1525,3650 1575,3650 1575,3700 1575,3750 1575,3800 1425,3850 1475,3850 1525,3850 1575,3850 1425,3900 1475,3900 1525,3900 1575,3900
BAL.CB_HI14: R727.1 R741.1 U600.18 | length 4662.5
  Top Copper w12: U600.18@3609.35,1760.93 3669.39,1760.93 v1(3678.45,1769.98)
  Top Copper w30: v1(1012.5,2987.5) 1750,2987.5 1787.5,3025 2225,3025 2252.69,2997.31 3057.37,2997.31 3154.68,2900 v1(3737.5,2900)
  Signal Layer 1 w30: 750,3287.5 750,3250 v1(1012.5,2987.5) ; v1(3737.5,2900) 3877.14,2760.36 v1(3877.14,1783.26)
  Signal Layer 2 w30: v1(3678.45,1769.98) 3691.85,1756.58 3846.22,1756.58 v1@3875.02,1785.38
  other v1: 650,3300 700,3300 750,3300 800,3300 800,3350 800,3400 800,3450 650,3500 700,3500 750,3500 800,3500 650,3550 700,3550 750,3550 800,3550 650,3600 700,3600 750,3600 800,3600 650,3650 700,3650 750,3650 800,3650 800,3700 800,3750 800,3800 650,3850 700,3850 750,3850 800,3850 650,3900 700,3900 750,3900 800,3900
BAL.CB_LO0: R714.1 R728.1 U600.38 | length 3361.7
  Top Copper w12: U600.38@3432.19,2115.26 3432.19,2207.19 v1(3450,2225)
  Signal Layer 1 w30: v1@4612.5,1787.5 4730.25,1905.25 4730.25,2229.48 5550,3049.23 v1(5550,3300)
  Signal Layer 2 w30: v1(3450,2225) 4063.27,2225 4385.58,1902.69 4497.31,1902.69 v1@4612.5,1787.5
  other v1: 4612.5,1783.26 5500,3300 5600,3300 5650,3300 5500,3350 5500,3400 5500,3450 5500,3500 5550,3500 5600,3500 5650,3500 5500,3550 5550,3550 5600,3550 5650,3550 5500,3600 5550,3600 5600,3600 5650,3600 5500,3650 5550,3650 5600,3650 5650,3650 5500,3700 5500,3750 5500,3800 5500,3850 5550,3850 5600,3850 5650,3850 5500,3900 5550,3900 5600,3900 5650,3900
BAL.CB_LO2: R716.1 R730.1 U600.35 | length 2942.5
  Top Copper w12: U600.35@3491.24,2115.26 3491.24,2150.6 3499.83,2159.19 3499.83,2174.83 v1(3500,2175)
  Signal Layer 1 w30: v1(4481.99,1783.26) 4365.19,1900.06 4365.19,2653.46 4579.81,2868.08 4579.81,3104.81 v1(4775,3300)
  Signal Layer 2 w30: v1(3500,2175) 4065.19,2175 4371.5,1868.69 4396.56,1868.69 v1(4481.99,1783.26)
  other v1: 4725,3300 4825,3300 4875,3300 4725,3350 4725,3400 4725,3450 4725,3500 4775,3500 4825,3500 4875,3500 4725,3550 4775,3550 4825,3550 4875,3550 4725,3600 4775,3600 4825,3600 4875,3600 4725,3650 4775,3650 4825,3650 4875,3650 4725,3700 4725,3750 4725,3800 4725,3850 4775,3850 4825,3850 4875,3850 4725,3900 4775,3900 4825,3900 4875,3900
BAL.CB_LO4: R718.1 R732.1 U600.32 | length 2527.2
  Top Copper w12: U600.32@3609.35,2036.52 3698.13,2036.52 3707.04,2027.61 v1(3710.19,2027.61)
  Signal Layer 1 w30: v1(4050,3300) 4050,3125 4212.55,2962.45 4212.55,2287.45 4297.19,2202.81 4297.19,1862.99 4312.5,1847.68 4312.5,1845.76 v1(4375,1783.26)
  Signal Layer 2 w30: v1(3710.19,2027.61) 3716.58,2034 4124.26,2034 v1(4375,1783.26)
  other v1: 3950,3300 4000,3300 4100,3300 3950,3350 3950,3400 3950,3450 3950,3500 4000,3500 4050,3500 4100,3500 3950,3550 4000,3550 4050,3550 4100,3550 3950,3600 4000,3600 4050,3600 4100,3600 3950,3650 4000,3650 4050,3650 4100,3650 3950,3700 3950,3750 3950,3800 3950,3850 4000,3850 4050,3850 4100,3850 3950,3900 4000,3900 4050,3900 4100,3900
BAL.CB_LO6: R720.1 R734.1 U600.29 | length 2982.3
  Top Copper w12: U600.29@3609.35,1977.46 3669.39,1977.46 3678.45,1968.41
  Top Copper w24: 3678.45,1968.41 3685.64,1968.41 3700.6,1983.37 3704.85,1983.37
  Top Copper w30: 3704.85,1983.37 4074.89,1983.37 v1(4275,1783.26)
  Signal Layer 1 w30: v1(3937.5,3137.5) 4144.55,2930.45 4144.55,2259.28 4229.19,2174.64 4229.19,1830.99 4275,1785.18 v1(4275,1783.26)
  Signal Layer 2 w30: v1(3275,3300) 3437.5,3137.5 v1(3937.5,3137.5)
  other v1: 3175,3300 3225,3300 3325,3300 3175,3350 3175,3400 3175,3450 3175,3500 3225,3500 3275,3500 3325,3500 3175,3550 3225,3550 3275,3550 3325,3550 3175,3600 3225,3600 3275,3600 3325,3600 3175,3650 3225,3650 3275,3650 3325,3650 3175,3700 3175,3750 3175,3800 3175,3850 3225,3850 3275,3850 3325,3850 3175,3900 3225,3900 3275,3900 3325,3900
BAL.CB_LO8: R722.1 R736.1 U600.26 | length 3550.1
  Top Copper w12: U600.26@3609.35,1918.41 3698.13,1918.41 3707.04,1909.5 v1(3710.19,1909.5)
  Signal Layer 1 w30: v1(3225,3087.5) 3283.9,3028.6 3906.98,3028.6 4076.55,2859.03 4076.55,2231.12 4161.19,2146.48 4161.19,1802.82 4175,1789.01 v1(4175,1783.26)
  Signal Layer 2 w30: v1(2500,3300) 2500,3275 2562.5,3212.5 3100,3212.5 v1(3225,3087.5) ; v1(3710.19,1909.5) 3805.66,1909.5 3823.98,1927.81 4069.5,1927.81 4175,1822.31 v1(4175,1783.26)
  other v1: 2400,3300 2450,3300 2550,3300 2400,3350 2400,3400 2400,3450 2400,3500 2450,3500 2500,3500 2550,3500 2400,3550 2450,3550 2500,3550 2550,3550 2400,3600 2450,3600 2500,3600 2550,3600 2400,3650 2450,3650 2500,3650 2550,3650 2400,3700 2400,3750 2400,3800 2400,3850 2450,3850 2500,3850 2550,3850 2400,3900 2450,3900 2500,3900 2550,3900
BAL.CB_LO10: R724.1 R738.1 U600.23 | length 4092.9
  Top Copper w12: U600.23@3609.35,1859.35 3669.39,1859.35 3678.45,1850.3
  Top Copper w24: 3678.45,1850.3 3686.61,1850.3 3697.01,1860.7 3726.8,1860.7
  Top Copper w30: 3726.8,1860.7 3997.56,1860.7 v1(4075,1783.26)
  Signal Layer 1 w30: v1(3025,3125) 3090.19,3125 3254.58,2960.6 3876.9,2960.6 4008.55,2828.95 4008.55,2202.95 4091,2120.5 4091,1799.26 v1(4075,1783.26)
  Signal Layer 2 w30: v1(1725,3300) 1725,3262.5 1775,3212.5 2289.42,3212.5 2376.92,3125 v1(3025,3125)
  other v1: 1625,3300 1675,3300 1775,3300 1625,3350 1625,3400 1625,3450 1625,3500 1675,3500 1725,3500 1775,3500 1625,3550 1675,3550 1725,3550 1775,3550 1625,3600 1675,3600 1725,3600 1775,3600 1625,3650 1675,3650 1725,3650 1775,3650 1625,3700 1625,3750 1625,3800 1625,3850 1675,3850 1725,3850 1775,3850 1625,3900 1675,3900 1725,3900 1775,3900
BAL.CB_LO12: R726.1 R740.1 U600.20 | length 4634.9
  Top Copper w12: U600.20@3609.35,1800.3 3698.13,1800.3 3707.04,1791.39 v1(3710.19,1791.39)
  Signal Layer 1 w30: v1(3850,2875) 3937.5,2787.5 v1(3937.5,1783.26)
  Signal Layer 2 w30: v1(900,3300) 1181,3019 1731.77,3019 1735.58,3015.19 2589.42,3015.19 2593.23,3019 3706,3019 v1(3850,2875) ; v1(3710.19,1791.39) 3831.8,1791.39 3865.41,1825 3920.76,1825 3937.5,1808.26 v1(3937.5,1783.26)
  other v1: 850,3300 950,3300 1000,3300 850,3350 850,3400 850,3450 850,3500 900,3500 950,3500 1000,3500 850,3550 900,3550 950,3550 1000,3550 850,3600 900,3600 950,3600 1000,3600 850,3650 900,3650 950,3650 1000,3650 850,3700 850,3750 850,3800 850,3850 900,3850 950,3850 1000,3850 850,3900 900,3900 950,3900 1000,3900
BAL_NTC0: C701.2 R613.1 R702.1 | length 1395.8
  Top Copper w16: R702.1@1690.06,3125 C701.2@1783.96,3125 ; v1(2675,2775) R613.1@2709.94,2775
  Signal Layer 1 w16: v1@1739.23,3123.27 1740.96,3123.27 1900,2964.23 v1(1900,2750)
  Signal Layer 2 w16: v1(1900,2750) 1901.46,2748.54 1901.46,2735.98 1927.75,2709.69 2267.69,2709.69 2333,2775 v1(2675,2775)
  other v1: 1739.23,3125
BAL_NTC1: C703.2 R614.1 R703.1 | length 2304.2
  Top Copper w16: v1(2675,2837.5) R614.1@2709.94,2837.5 ; C703.2@4491.04,3125 v1(4537.5,3125) R703.1@4584.94,3125
  Signal Layer 1 w16: v1(4537.5,2875) 4537.5,2984.69 4552.81,3000 4552.81,3109.69 v1(4537.5,3125)
  Signal Layer 2 w16: v1(2675,2837.5) 2781.57,2837.5 2790.94,2846.87 2790.94,2849.02 2807.23,2865.31 2830.27,2865.31 2870.58,2825 4487.5,2825 v1(4537.5,2875)
CIN0: C526.2 J300.13 R513.2 R706.1 R714.2 R728.2 | length 4642.8
  Top Copper w16: v1(4075,988.04) 4075,1101.24 4102.3,1128.54 C526.2@4125,1128.54 R513.2@4125,1197.44
  Signal Layer 1 w16: v1(4075,988.04) 4094.49,968.55 J300.13@4094.49,487.99
  Bot Copper w30: J300.13@4094.49,487.99 4240.19,633.69 4240.19,1302.69 4465.19,1527.69 4476.92,1527.69 4497.31,1548.08 4497.31,1572.31 4897.31,1972.31 5486.6,1972.31 5850,2335.71 v1(5850,3300)
  other v1: 5700,3300 5750,3300 5800,3300 5900,3300 5950,3300 6000,3300 6050,3300 6100,3300 6150,3300 6200,3300 6250,3300 5850,3350 5900,3350 5950,3350 6000,3350 6050,3350 6100,3350 6150,3350 6200,3350 6250,3350 5850,3400 5900,3400 5950,3400 6000,3400 6050,3400 6100,3400 6150,3400 6200,3400 6250,3400 5850,3450 5900,3450 5950,3450 6250,3450 5700,3500 5750,3500 5800,3500 5850,3500 5700,3550 5750,3550 5800,3550 5700,3600 5750,3600 5800,3600 5700,3650 5750,3650 5700,3850 5750,3850 5800,3850 5700,3900 5750,3900 5800,3900
CIN1: C522.2 J300.2 R511.2 U600.37 | length 2676.2
  Top Copper w12: v1@3451.87,2051.87 U600.37@3451.87,2115.26
  Top Copper w16: v1(3975,988.04) 3975,1101.24 4002.3,1128.54 C522.2@4025,1128.54 R511.2@4025,1197.44
  Signal Layer 1 w30: v1@3975,2125 3979.81,2120.19 3979.81,1014.8 3975,1009.99 v1(3975,988.04) 4037.5,925.54 4037.5,431.52 J300.2@3975.98,370
  Signal Layer 2 w30: v1(3451.87,2050) 3526.87,2125 v1(3979.81,2125)
CIN2: C518.2 J300.14 R509.2 R707.1 R715.1 R716.2 R729.1 R730.2 | length 4324.4
  Top Copper w16: v1(3875,988.04) 3875,1101.24 3902.3,1128.54 C518.2@3925,1128.54 R509.2@3925,1197.44
  Signal Layer 1 w16: v1(3875,988.04) 3875,662.5 3975.98,561.52 J300.14@3975.98,487.99
  Bot Copper w30: J300.14@3975.98,487.99 3975.98,682.76 3984.81,691.58 3984.81,878.23 v1(3875,988.04) 3875,1313.27 3990.19,1428.46 3990.19,2086.15 4212.5,2308.46 4212.5,2725 4452.02,2964.52 4752.02,2964.52 v1(5087.5,3300)
  other v1: 4925,3300 4965.62,3300 5006.25,3300 5046.87,3300 5128.12,3300 5168.75,3300 5209.37,3300 5250,3300 5046.87,3350 5087.5,3350 5128.12,3350 5046.87,3400 5087.5,3400 5128.12,3400 5046.87,3450 5087.5,3450 5128.12,3450 4925,3500 4965.62,3500 5006.25,3500 5046.87,3500 5087.5,3500 5128.12,3500 5168.75,3500 5209.37,3500 5250,3500 4925,3550 4965.62,3550 5006.25,3550 5046.87,3550 5087.5,3550 5128.12,3550 5168.75,3550 5209.37,3550 5250,3550 4925,3600 4965.62,3600 5006.25,3600 5046.87,3600 5087.5,3600 5128.12,3600 5168.75,3600 5209.37,3600 5250,3600 4925,3650 4965.62,3650 5006.25,3650 5046.87,3650 5087.5,3650 5128.12,3650 5168.75,3650 5209.37,3650 5250,3650 5046.87,3700 5087.5,3700 5128.12,3700 5046.87,3750 5087.5,3750 5128.12,3750 5046.87,3800 5087.5,3800 5128.12,3800 4925,3850 4965.62,3850 5006.25,3850 5046.87,3850 5087.5,3850 5128.12,3850 5168.75,3850 5209.37,3850 5250,3850 4925,3900 4965.62,3900 5006.25,3900 5046.87,3900 5087.5,3900 5128.12,3900 5168.75,3900 5209.37,3900 5250,3900
CIN3: C514.2 J300.3 R507.2 U600.34 | length 2365.8
  Top Copper w12: v1@3510.93,2051.87 U600.34@3510.93,2115.26
  Top Copper w16: v1(3775,988.04) 3775,1101.24 3802.3,1128.54 C514.2@3825,1128.54 R507.2@3825,1197.44
  Signal Layer 1 w30: v1(3775,2075) 3775,659.22 3912.5,521.72 3912.5,424.51 J300.3@3857.99,370
  Signal Layer 2 w30: v1(3510.93,2050) 3535.93,2075 v1(3775,2075)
